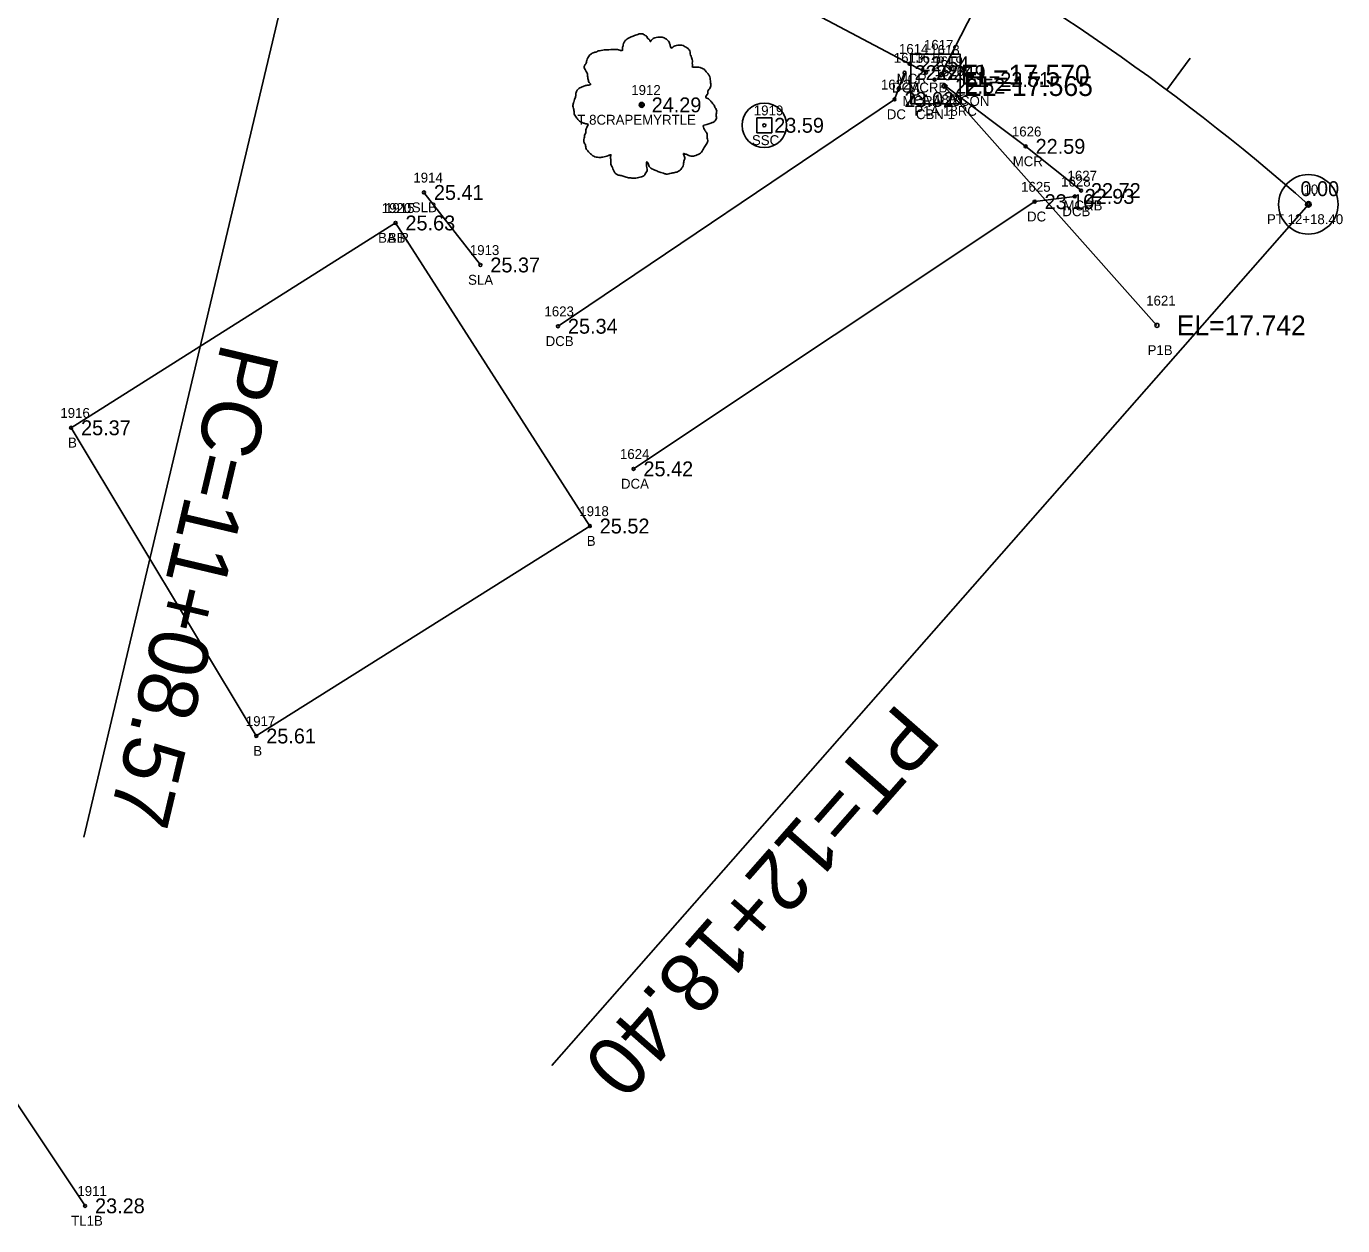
# Model space of a CAD drawing. Extents: x 2654414 to 2656963, y 761776 to 764965.
# Drawn here: x 2655683.5 to 2655816.4, y 762606.2 to 762727.3 of the extents above; entities that cross this region are included whole.
import ezdxf

# ---------------------------------------------------------------- set-up
doc = ezdxf.new("R2010")
doc.units = 0
for name, color, linetype in [('RD_EX_Bldg', 7, 'Continuous'), ('RD_EX_Bldg_txCode', 7, 'Continuous'), ('RD_EX_Conc', 7, 'Continuous'), ('RD_EX_Conc_txCode', 7, 'Continuous'), ('RD_EX_DR_Inlet', 7, 'Continuous'), ('RD_EX_DR_Inlet_txCode', 7, 'Continuous'), ('RD_EX_DR_Pipe', 7, 'Continuous'), ('RD_EX_DR_Pipe_txCode', 7, 'Continuous'), ('RD_EX_TX_Bldg_ELEV', 7, 'Continuous'), ('RD_EX_TX_Conc_ELEV', 7, 'Continuous'), ('RD_EX_TX_DR_Inlet_ELEV', 7, 'Continuous'), ('RD_EX_TX_UT_ELEV', 7, 'Continuous'), ('RD_EX_TX_VEG_ELEV', 7, 'Continuous'), ('RD_EX_UT', 7, 'Continuous'), ('RD_EX_UT_txCode', 7, 'Continuous'), ('RD_EX_VEG', 7, 'Continuous'), ('RD_EX_VEG_txCode', 7, 'Continuous'), ('RD_HC_Cl', 7, 'Continuous'), ('RD_HC_Data', 7, 'Continuous'), ('RD_HC_Data_Tic', 7, 'Continuous'), ('RD_HC_Survey_ELEV', 7, 'Continuous'), ('RD_HC_txCode', 7, 'Continuous'), ('RD_SMD_Locator', 7, 'Continuous'), ('RD_TX_Pipe_ElevEX', 7, 'Continuous')]:
    doc.layers.add(name, color=color, linetype=linetype)

msp = doc.modelspace()

# ---------------------------------------------------------------- linework, layer by layer
at = {"layer": 'RD_EX_Bldg'}
msp.add_lwpolyline([(2655720.78, 762707.43), (2655688.04, 762686.75), (2655706.73, 762655.63), (2655740.39, 762676.83), (2655720.78, 762707.43)], dxfattribs=at)
at = {"layer": 'RD_EX_Conc'}
for points in [[(2655638.83, 762758.42), (2655640.65, 762759.07), (2655648.88, 762760.53), (2655656.27, 762760.57), (2655663.1, 762759.53), (2655700.27, 762751.26), (2655744.39, 762738.46), (2655772.67, 762723.5), (2655774.32, 762722.61)], [(2655772.16, 762722.6), (2655771.14, 762719.9), (2655737.18, 762697)], [(2655776.29, 762721.25), (2655784.38, 762715.16), (2655789.97, 762710.7)], [(2655744.8, 762682.6), (2655785.29, 762709.58), (2655789.33, 762710.11)]]:
    msp.add_lwpolyline(points, dxfattribs=at)
at = {"layer": 'RD_EX_DR_Inlet'}
msp.add_line((2655777.78, 762719.46), (2655777.78, 762724.46), dxfattribs=at)
msp.add_lwpolyline([(2655777.78, 762719.46), (2655777.78, 762724.46), (2655772.78, 762724.46), (2655772.78, 762719.46)], close=True, dxfattribs=at)
at = {"layer": 'RD_EX_DR_Pipe'}
for p, q in [((2655775.82, 762722.4), (2655786.51, 762743.29)), ((2655776.15, 762721.25), (2655797.63, 762697.09))]:
    msp.add_line(p, q, dxfattribs=at)
at = {"layer": 'RD_EX_UT'}
for p, q in [((2655758.75, 762718.04), (2655757.25, 762718.04)), ((2655757.25, 762718.04), (2655757.25, 762716.54)), ((2655758.75, 762716.54), (2655758.75, 762718.04)), ((2655757.25, 762716.54), (2655758.75, 762716.54))]:
    msp.add_line(p, q, dxfattribs=at)
msp.add_circle((2655758, 762717.29), 2.25, dxfattribs=at)
at = {"layer": 'RD_EX_VEG'}
msp.add_line((2655729.35, 762703.19), (2655723.65, 762710.51), dxfattribs=at)
msp.add_lwpolyline([(2655649.21, 762686), (2655656.35, 762657.8), (2655689.45, 762608.19)], dxfattribs=at)
for centre, radius in [((2655745.63, 762719.35), 0.25), ((2655745.62, 762719.33), 0.0001)]:
    msp.add_circle(centre, radius, dxfattribs=at)
for points in [[(2655745.77, 762726.52), (2655745.47, 762726.54), (2655745.14, 762726.44), (2655744.89, 762726.34), (2655744.67, 762726.27), (2655744.44, 762726.17), (2655744.14, 762725.99), (2655743.92, 762725.79), (2655743.79, 762725.54), (2655743.74, 762725.32), (2655743.69, 762725.04), (2655743.69, 762724.87), (2655743.57, 762724.84), (2655743.42, 762724.87), (2655743.17, 762724.94), (2655742.92, 762724.94), (2655742.67, 762724.94), (2655742.32, 762724.92), (2655741.97, 762724.92), (2655741.69, 762724.87), (2655741.37, 762724.82), (2655740.99, 762724.69), (2655740.64, 762724.57), (2655740.34, 762724.32), (2655740.09, 762723.84), (2655739.97, 762723.49), (2655739.82, 762723.24), (2655739.97, 762722.8), (2655740.14, 762722.45), (2655740.17, 762722.25), (2655740.24, 762721.82), (2655740.34, 762721.6), (2655740.47, 762721.4), (2655740.39, 762721.37), (2655740.02, 762721.32), (2655739.72, 762721.22), (2655739.29, 762721), (2655739.07, 762720.77), (2655738.97, 762720.45), (2655738.94, 762720.1), (2655738.84, 762719.9), (2655738.77, 762719.62), (2655738.74, 762719.55), (2655738.69, 762719.22), (2655738.79, 762718.77), (2655738.82, 762718.42), (2655738.94, 762718.2), (2655739.09, 762718.02), (2655739.27, 762717.77), (2655739.67, 762717.55), (2655739.99, 762717.45), (2655740.19, 762717.42), (2655740.02, 762716.92), (2655739.97, 762716.57), (2655739.84, 762716.17), (2655739.84, 762716.1), (2655739.79, 762715.62), (2655739.94, 762715.3), (2655740.02, 762714.92), (2655740.19, 762714.7), (2655740.47, 762714.4), (2655740.79, 762714.17), (2655741.29, 762714.05), (2655741.69, 762714.07), (2655742.27, 762714.25), (2655742.52, 762714.32), (2655742.49, 762714.15), (2655742.52, 762713.77), (2655742.52, 762713.35), (2655742.67, 762713.02), (2655742.77, 762712.75), (2655742.92, 762712.5), (2655743.24, 762712.27), (2655743.64, 762712.2), (2655744.07, 762712.05), (2655744.52, 762711.97), (2655745.02, 762711.95), (2655745.62, 762712.1), (2655745.89, 762712.22), (2655745.99, 762712.4), (2655746.19, 762712.77), (2655746.14, 762713), (2655746.17, 762713.6), (2655746.27, 762713.42), (2655746.44, 762713.07), (2655746.94, 762712.77), (2655747.34, 762712.6), (2655747.81, 762712.45), (2655748.11, 762712.37), (2655748.59, 762712.45), (2655748.96, 762712.52), (2655749.34, 762712.65), (2655749.64, 762712.92), (2655749.81, 762713.2), (2655749.86, 762713.47), (2655749.94, 762713.85), (2655749.99, 762714.02)], [(2655749.99, 762714.02), (2655749.91, 762714.2), (2655749.86, 762714.45), (2655749.94, 762714.42), (2655750.11, 762714.37), (2655750.39, 762714.25), (2655750.61, 762714.17), (2655750.94, 762714.2), (2655751.21, 762714.3), (2655751.66, 762714.57), (2655751.94, 762715.05), (2655752.21, 762715.45), (2655752.29, 762715.77), (2655752.24, 762716), (2655752.21, 762716.5), (2655752.01, 762716.75), (2655751.96, 762716.87), (2655751.86, 762717.27), (2655751.94, 762717.32), (2655752.21, 762717.37), (2655752.59, 762717.5), (2655752.86, 762717.62), (2655753.09, 762717.8), (2655753.16, 762718.02), (2655753.14, 762718.42), (2655753.19, 762718.82), (2655753.11, 762718.97), (2655753.01, 762719.12), (2655752.94, 762719.32), (2655752.79, 762719.47), (2655752.69, 762719.62), (2655752.59, 762719.72), (2655752.46, 762719.87), (2655752.29, 762720), (2655752.14, 762720.05), (2655752.09, 762720.2), (2655752.24, 762720.4), (2655752.29, 762720.5), (2655752.31, 762720.72), (2655752.54, 762721.07), (2655752.59, 762721.47), (2655752.54, 762721.9), (2655752.49, 762722.17), (2655752.34, 762722.45), (2655752.14, 762722.7), (2655752.01, 762722.87), (2655751.84, 762723), (2655751.51, 762723.12), (2655751.26, 762723.17), (2655750.91, 762723.17), (2655750.71, 762723.22), (2655750.74, 762723.27), (2655750.74, 762723.42), (2655750.74, 762723.69), (2655750.66, 762724.14), (2655750.51, 762724.64), (2655750.51, 762724.67), (2655750.41, 762724.92), (2655750.19, 762725.12), (2655750.01, 762725.22), (2655749.81, 762725.34), (2655749.56, 762725.37), (2655749.26, 762725.37), (2655748.99, 762725.32), (2655748.79, 762725.22), (2655748.61, 762725.09), (2655748.54, 762725.24), (2655748.44, 762725.54), (2655748.39, 762725.69), (2655748.24, 762725.87), (2655748.01, 762726.07), (2655747.56, 762726.19), (2655746.94, 762726.12), (2655746.64, 762725.92), (2655746.49, 762725.74), (2655746.44, 762725.87), (2655746.24, 762726.07), (2655746.14, 762726.24), (2655745.97, 762726.37), (2655745.82, 762726.47), (2655745.72, 762726.52)]]:
    msp.add_spline(points, degree=3, dxfattribs=at)
at = {"layer": 'RD_HC_Cl'}
msp.add_arc((2655664.41, 762540.27), 225, 48.7013, 76.6686, dxfattribs=at)
at = {"layer": 'RD_HC_Data'}
for p, q in [((2655716.3, 762759.21), (2655689.33, 762645.42)), ((2655812.91, 762709.31), (2655736.54, 762622.37))]:
    msp.add_line(p, q, dxfattribs=at)
for radius in [3, 0.282]:
    msp.add_circle((2655812.91, 762709.31), radius, dxfattribs=at)
at = {"layer": 'RD_HC_Data_Tic'}
msp.add_line((2655798.61, 762720.87), (2655800.99, 762724.08), dxfattribs=at)
at = {"layer": 'RD_SMD_Locator'}
for centre, radius in [((2655772.16, 762722.6), 0.15), ((2655772.67, 762723.5), 0.15), ((2655774.32, 762722.61), 0.15), ((2655775.19, 762721.91), 0.15), ((2655775.82, 762722.4), 0.2), ((2655776.15, 762721.25), 0.2), ((2655776.29, 762721.25), 0.15), ((2655771.14, 762719.9), 0.15), ((2655745.63, 762719.35), 0.15), ((2655758, 762717.29), 0.15), ((2655784.38, 762715.16), 0.15), ((2655789.97, 762710.7), 0.15), ((2655723.65, 762710.51), 0.15), ((2655785.29, 762709.58), 0.15), ((2655789.33, 762710.11), 0.15), ((2655812.91, 762709.31), 0.15), ((2655720.78, 762707.43), 0.15), ((2655720.78, 762707.43), 0.15), ((2655729.35, 762703.19), 0.15), ((2655737.18, 762697), 0.15), ((2655797.63, 762697.09), 0.2), ((2655688.04, 762686.75), 0.15), ((2655744.8, 762682.6), 0.15), ((2655740.39, 762676.83), 0.15), ((2655706.73, 762655.63), 0.15), ((2655689.45, 762608.19), 0.15)]:
    msp.add_circle(centre, radius, dxfattribs=at)

# ---------------------------------------------------------------- texts
at = {"layer": 'RD_EX_Bldg_txCode'}
for s, p in [('1920', (2655719.39, 762708.43)), ('1915', (2655719.72, 762708.43)), ('BA R', (2655719.02, 762705.43)), ('BB', (2655720, 762705.43)), ('1916', (2655686.95, 762687.75)), ('B', (2655687.73, 762684.75)), ('1918', (2655739.33, 762677.83)), ('B', (2655740.08, 762674.83)), ('1917', (2655705.67, 762656.63)), ('B', (2655706.42, 762653.63))]:
    msp.add_text(s, height=1, dxfattribs=at).set_placement(p)
at = {"layer": 'RD_EX_Conc_txCode'}
for s, p in [('1614', (2655771.59, 762724.5)), ('1613', (2655771.07, 762723.6)), ('1615', (2655773.23, 762723.61)), ('1616', (2655775.18, 762722.25)), ('1622', (2655769.77, 762720.9)), ('DCA', (2655770.89, 762720.6)), ('MCR', (2655771.36, 762721.5)), ('MCRB', (2655772.53, 762720.61)), ('MCRA 18CON', (2655771.95, 762719.25)), ('DC', (2655770.36, 762717.9)), ('1626', (2655782.99, 762716.16)), ('MCR', (2655783.07, 762713.16)), ('1628', (2655787.96, 762711.11)), ('1627', (2655788.6, 762711.7)), ('1625', (2655783.92, 762710.58)), ('MCRB', (2655788.19, 762708.7)), ('DC', (2655784.51, 762707.58)), ('DCB', (2655788.08, 762708.11)), ('1623', (2655735.81, 762698)), ('DCB', (2655735.93, 762695)), ('1624', (2655743.43, 762683.6)), ('DCA', (2655743.53, 762680.6))]:
    msp.add_text(s, height=1, dxfattribs=at).set_placement(p)
at = {"layer": 'RD_EX_DR_Inlet_txCode'}
for s, p in [('1617', (2655774.11, 762724.91)), ('CBN 1', (2655773.3, 762717.91))]:
    msp.add_text(s, height=1, dxfattribs=at).set_placement(p)
at = {"layer": 'RD_EX_DR_Pipe_txCode'}
for s, p in [('1618', (2655774.74, 762724.4)), ('1619', (2655775.06, 762723.25)), ('PA 18RC', (2655772.98, 762719.4)), ('P1A 18RC', (2655773.14, 762718.25)), ('1621', (2655796.54, 762699.09)), ('P1B', (2655796.68, 762694.09))]:
    msp.add_text(s, height=1, dxfattribs=at).set_placement(p)
at = {"layer": 'RD_EX_TX_Bldg_ELEV'}
for s, p in [('25.63', (2655721.78, 762706.68)), ('25.63', (2655721.78, 762706.68)), ('25.37', (2655689.04, 762686)), ('25.52', (2655741.39, 762676.08)), ('25.61', (2655707.73, 762654.88))]:
    msp.add_text(s, height=1.5, dxfattribs=at).set_placement(p)
at = {"layer": 'RD_EX_TX_Conc_ELEV'}
for s, p in [('22.54', (2655773.67, 762722.75)), ('22.82', (2655773.16, 762721.85)), ('22.49', (2655775.32, 762721.86)), ('22.52', (2655777.29, 762720.5)), ('23.02', (2655772.14, 762719.15)), ('22.59', (2655785.38, 762714.41)), ('22.93', (2655790.33, 762709.36)), ('22.72', (2655790.97, 762709.95)), ('23.10', (2655786.29, 762708.83)), ('25.34', (2655738.18, 762696.25)), ('25.42', (2655745.8, 762681.85))]:
    msp.add_text(s, height=1.5, dxfattribs=at).set_placement(p)
at = {"layer": 'RD_EX_TX_DR_Inlet_ELEV'}
msp.add_text('EL=22.51', height=1.5, dxfattribs=at).set_placement((2655778.19, 762721.16))
at = {"layer": 'RD_EX_TX_UT_ELEV'}
msp.add_text('23.59', height=1.5, dxfattribs=at).set_placement((2655759, 762716.54))
at = {"layer": 'RD_EX_TX_VEG_ELEV'}
for s, p in [('24.29', (2655746.63, 762718.6)), ('25.41', (2655724.65, 762709.76)), ('25.37', (2655730.35, 762702.44)), ('23.28', (2655690.45, 762607.44))]:
    msp.add_text(s, height=1.5, dxfattribs=at).set_placement(p)
at = {"layer": 'RD_EX_UT_txCode'}
for s, p in [('1919', (2655756.94, 762718.29)), ('SSC', (2655756.75, 762715.29))]:
    msp.add_text(s, height=1, dxfattribs=at).set_placement(p)
at = {"layer": 'RD_EX_VEG_txCode'}
for s, p in [('1912', (2655744.57, 762720.35)), ('T 8CRAPEMYRTLE', (2655739.13, 762717.35)), ('1914', (2655722.58, 762711.51)), ('SLB', (2655722.42, 762708.51)), ('1913', (2655728.28, 762704.19)), ('SLA', (2655728.1, 762701.19)), ('1911', (2655688.67, 762609.19)), ('TL1B', (2655688.04, 762606.19))]:
    msp.add_text(s, height=1, dxfattribs=at).set_placement(p)
at = {"layer": 'RD_HC_Data'}
for s, rotation, p in [('PC=11+08.57', 256.6686, (2655703.25, 762695.5)), ('PT=12+18.40', 228.7013, (2655771.52, 762659.15))]:
    msp.add_text(s, height=6, rotation=rotation, dxfattribs=at).set_placement(p)
at = {"layer": 'RD_HC_Survey_ELEV'}
msp.add_text('0.00', height=1.5, dxfattribs=at).set_placement((2655812.11, 762710.14))
at = {"layer": 'RD_HC_txCode'}
for s, p in [('10', (2655812.42, 762710.31)), ('PT 12+18.40', (2655808.73, 762707.31))]:
    msp.add_text(s, height=1, dxfattribs=at).set_placement(p)
at = {"layer": 'RD_TX_Pipe_ElevEX'}
for s, p in [('EL=17.570', (2655777.82, 762721.4)), ('EL=17.565', (2655778.15, 762720.25)), ('EL=17.742', (2655799.63, 762696.09))]:
    msp.add_text(s, height=2, dxfattribs=at).set_placement(p)

doc.saveas('drawing.dxf')
